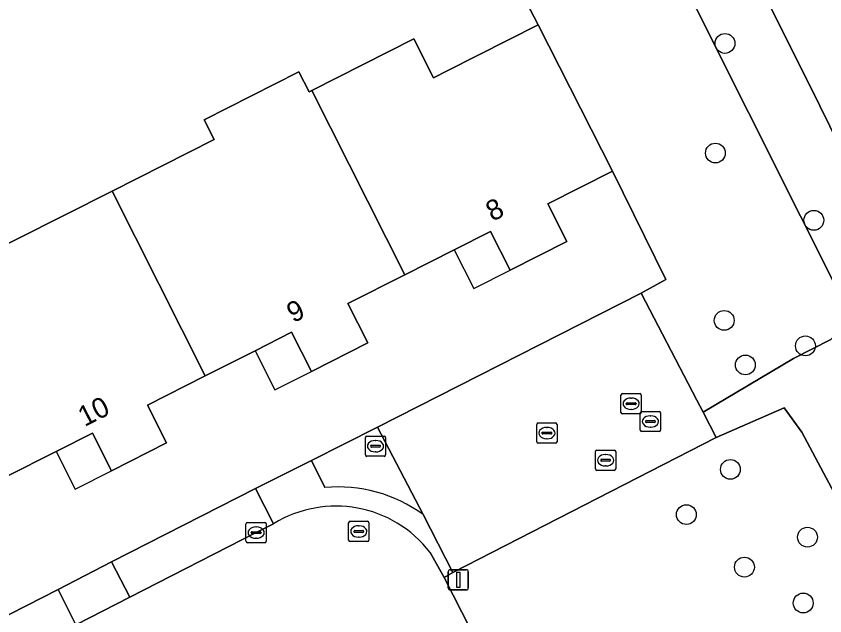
# Model space of a CAD drawing. Extents: x 162722 to 165104, y 384719 to 386284.
# Drawn here: x 163765.77 to 163805.66, y 385010 to 385039.57 of the extents above; entities that cross this region are included whole.
import ezdxf

# ---------------------------------------------------------------- set-up
doc = ezdxf.new("R2010")
doc.units = 0
for name, color, linetype in [('IMGEO_Boom', 7, 'Continuous'), ('IMGEO_Brandkraan', 7, 'Continuous'), ('IMGEO_Erf', 7, 'Continuous'), ('IMGEO_Groenvoorziening', 7, 'Continuous'), ('IMGEO_Kolk', 7, 'Continuous'), ('IMGEO_Lichtmast', 7, 'Continuous'), ('IMGEO_Pand', 7, 'Continuous'), ('IMGEO_Pand_nummerreeks', 7, 'Continuous'), ('IMGEO_Pand_overbouw', 7, 'Continuous'), ('IMGEO_Rijbaan_lokaal_open', 7, 'Continuous'), ('IMGEO_Rioolput', 7, 'Continuous'), ('IMGEO_Voetpad_open', 7, 'Continuous')]:
    doc.layers.add(name, color=color, linetype=linetype)

msp = doc.modelspace()

# ---------------------------------------------------------------- linework, layer by layer
at = {"layer": 'IMGEO_Boom'}
for centre in [(163800.734, 385038.222), (163800.261, 385032.816), (163805.118, 385029.501), (163800.696, 385024.566), (163804.702, 385023.309), (163801.74, 385022.369), (163801.001, 385017.219), (163798.83, 385014.99), (163804.803, 385013.876), (163801.694, 385012.4), (163804.593, 385010.631)]:
    msp.add_circle(centre, 0.489, dxfattribs=at)
at = {"layer": 'IMGEO_Brandkraan'}
for p, q in [((163782.997, 385017.937), (163782.997, 385018.789)), ((163783.072, 385018.863), (163783.924, 385018.863)), ((163783.998, 385018.789), (163783.998, 385017.937)), ((163783.256, 385018.357), (163783.256, 385018.369)), ((163783.694, 385018.32), (163783.296, 385018.32)), ((163783.299, 385018.406), (163783.697, 385018.406)), ((163783.485, 385018.643), (163783.51, 385018.643)), ((163783.74, 385018.369), (163783.74, 385018.357)), ((163783.924, 385017.863), (163783.072, 385017.863)), ((163783.508, 385018.083), (163783.483, 385018.083))]:
    msp.add_line(p, q, dxfattribs=at)
for points in [[(163782.997, 385017.937), (163782.997, 385018.789)], [(163783.072, 385018.863), (163783.924, 385018.863)], [(163783.998, 385018.789), (163783.998, 385017.937)], [(163783.924, 385017.863), (163783.072, 385017.863)]]:
    msp.add_lwpolyline(points, dxfattribs=at)
for centre, radius, start, end in [((163783.074, 385018.787), 0.0765, 91.552, 178.448), ((163783.074, 385018.787), 0.0765, 91.552, 178.448), ((163783.922, 385018.787), 0.0765, 1.552, 88.448), ((163783.922, 385018.787), 0.0765, 1.552, 88.448), ((163783.296, 385018.366), 0.0403, 85.8775, 175.7526), ((163783.293, 385018.356), 0.0366, 178.938, 274.7102), ((163783.697, 385018.363), 0.043, 264.8664, 352.4533), ((163783.701, 385018.368), 0.0386, 1.7309, 96.639), ((163783.074, 385017.939), 0.0765, 181.552, 268.448), ((163783.074, 385017.939), 0.0765, 181.552, 268.448), ((163783.922, 385017.939), 0.0765, 271.552, 358.448), ((163783.922, 385017.939), 0.0765, 271.552, 358.448)]:
    msp.add_arc(centre, radius, start, end, dxfattribs=at)
for centre, major_axis, ratio, start_param, end_param in [((163783.484, 385018.363), (-0.387, 0.002), 0.722429, 4.712389, 7.853982), ((163783.509, 385018.363), (-0.39, 0.002), 0.717154, 1.570796, 4.712389)]:
    msp.add_ellipse(centre, major_axis=major_axis, ratio=ratio, start_param=start_param, end_param=end_param, dxfattribs=at)
at = {"layer": 'IMGEO_Erf'}
for points in [[(163760.67, 385025.961), (163765.78, 385028.549), (163770.511, 385030.931), (163775.544, 385033.48), (163775.048, 385034.459), (163779.723, 385036.826), (163780.224, 385035.836), (163780.362, 385035.906), (163785.38, 385038.447), (163786.353, 385036.525), (163787.066, 385036.886), (163791.526, 385039.145), (163783.871, 385053.812)], [(163757.517, 385006.039), (163767.841, 385011.304), (163770.469, 385012.653), (163777.584, 385016.272), (163780.334, 385017.664), (163783.595, 385019.308), (163796.607, 385025.906), (163797.817, 385026.586), (163795.181, 385031.929), (163791.999, 385030.318), (163792.939, 385028.461), (163790.137, 385027.041), (163789.168, 385028.956), (163787.381, 385028.051), (163784.94, 385026.815), (163782.132, 385025.393), (163783.112, 385023.456), (163780.34, 385022.052), (163779.361, 385023.985), (163777.559, 385023.072), (163775.097, 385021.825), (163772.25, 385020.384), (163773.192, 385018.525), (163770.481, 385017.153), (163769.542, 385019.006), (163767.743, 385018.107), (163765.26, 385016.849)]]:
    msp.add_lwpolyline(points, dxfattribs=at)
at = {"layer": 'IMGEO_Groenvoorziening'}
msp.add_lwpolyline([(163776.799, 385086.81), (163778.131, 385085.393), (163779.162, 385082.093), (163791.359, 385057.157), (163791.535, 385054.401), (163792.881, 385051.428), (163794.209, 385050.139), (163807.026, 385024.596), (163808.566, 385025.713), (163809.035, 385026.84), (163808.847, 385028.154), (163805.421, 385035.138), (163798.727, 385048.566), (163793.575, 385058.788), (163790.143, 385065.128), (163788.181, 385067.57), (163786.027, 385073.647), (163785.482, 385074.719), (163784.543, 385076.561), (163782.934, 385079.72), (163780.143, 385084.723), (163778.682, 385086.223), (163777.874, 385086.761)], close=True, dxfattribs=at)
for points in [[(163783.871, 385053.812), (163791.526, 385039.145), (163795.181, 385031.929), (163797.817, 385026.586), (163796.607, 385025.906), (163799.345, 385020.634), (163799.657, 385020.033), (163804.115, 385022.684), (163805.95, 385023.625), (163807.026, 385024.596), (163794.209, 385050.139)], [(163798.727, 385048.566), (163805.421, 385035.138), (163808.847, 385028.154), (163809.035, 385026.84), (163808.566, 385025.713), (163807.026, 385024.596), (163805.95, 385023.625), (163804.115, 385022.684), (163799.657, 385020.033), (163800.305, 385018.786), (163803.653, 385020.249), (163804.532, 385019.055), (163810.006, 385008.789), (163813.545, 385004.677), (163817.003, 384998.463), (163818.75, 384994.205), (163821.467, 384989.96), (163821.501, 384989.907), (163826.306, 384989.862), (163827.686, 384987.569), (163834.379, 384974.661), (163840.9, 384963.114), (163856.826, 384929.784)], [(163810.006, 385008.789), (163804.532, 385019.055), (163803.653, 385020.249), (163800.305, 385018.786), (163787.306, 385012.139), (163786.877, 385011.884), (163792.143, 385001.568), (163792.25, 385001.396), (163802.343, 385006.509), (163805.625, 385000), (163810.019, 384991.283)]]:
    msp.add_lwpolyline(points, dxfattribs=at)
at = {"layer": 'IMGEO_Kolk'}
for p, q in [((163791.524, 385019.508), (163792.376, 385019.508)), ((163791.449, 385018.582), (163791.449, 385019.434)), ((163791.937, 385019.288), (163791.962, 385019.288)), ((163792.45, 385019.434), (163792.45, 385018.582)), ((163791.708, 385019.002), (163791.708, 385019.014)), ((163792.146, 385018.965), (163791.748, 385018.965)), ((163791.751, 385019.051), (163792.149, 385019.051)), ((163791.96, 385018.728), (163791.935, 385018.728)), ((163792.192, 385019.014), (163792.192, 385019.002)), ((163792.376, 385018.508), (163791.524, 385018.508)), ((163777.11, 385013.676), (163777.11, 385014.528)), ((163777.185, 385014.602), (163778.037, 385014.602)), ((163777.598, 385014.382), (163777.623, 385014.382)), ((163778.111, 385014.528), (163778.111, 385013.676)), ((163777.369, 385014.096), (163777.369, 385014.108)), ((163777.807, 385014.059), (163777.409, 385014.059)), ((163777.412, 385014.145), (163777.81, 385014.145)), ((163777.853, 385014.108), (163777.853, 385014.096)), ((163778.037, 385013.602), (163777.185, 385013.602)), ((163777.621, 385013.822), (163777.596, 385013.822))]:
    msp.add_line(p, q, dxfattribs=at)
for points in [[(163791.524, 385019.508), (163792.376, 385019.508)], [(163791.449, 385018.582), (163791.449, 385019.434)], [(163792.45, 385019.434), (163792.45, 385018.582)], [(163792.376, 385018.508), (163791.524, 385018.508)], [(163777.11, 385013.676), (163777.11, 385014.528)], [(163777.185, 385014.602), (163778.037, 385014.602)], [(163778.111, 385014.528), (163778.111, 385013.676)], [(163778.037, 385013.602), (163777.185, 385013.602)]]:
    msp.add_lwpolyline(points, dxfattribs=at)
for centre, radius, start, end in [((163791.526, 385019.432), 0.0765, 91.552, 178.448), ((163791.526, 385019.432), 0.0765, 91.552, 178.448), ((163792.374, 385019.432), 0.0765, 1.552, 88.448), ((163792.374, 385019.432), 0.0765, 1.552, 88.448), ((163791.748, 385019.011), 0.0403, 85.8775, 175.7526), ((163791.745, 385019.001), 0.0366, 178.938, 274.7102), ((163792.149, 385019.008), 0.043, 264.8664, 352.4533), ((163792.153, 385019.013), 0.0386, 1.7309, 96.639), ((163791.526, 385018.584), 0.0765, 181.552, 268.448), ((163791.526, 385018.584), 0.0765, 181.552, 268.448), ((163792.374, 385018.584), 0.0765, 271.552, 358.448), ((163792.374, 385018.584), 0.0765, 271.552, 358.448), ((163777.187, 385014.526), 0.0765, 91.552, 178.448), ((163777.187, 385014.526), 0.0765, 91.552, 178.448), ((163778.035, 385014.526), 0.0765, 1.552, 88.448), ((163778.035, 385014.526), 0.0765, 1.552, 88.448), ((163777.409, 385014.105), 0.0403, 85.8775, 175.7526), ((163777.406, 385014.095), 0.0366, 178.938, 274.7102), ((163777.81, 385014.102), 0.043, 264.8664, 352.4533), ((163777.814, 385014.107), 0.0386, 1.7309, 96.639), ((163777.187, 385013.678), 0.0765, 181.552, 268.448), ((163777.187, 385013.678), 0.0765, 181.552, 268.448), ((163778.035, 385013.678), 0.0765, 271.552, 358.448), ((163778.035, 385013.678), 0.0765, 271.552, 358.448)]:
    msp.add_arc(centre, radius, start, end, dxfattribs=at)
for centre, major_axis, ratio, start_param, end_param in [((163791.936, 385019.008), (-0.387, 0.002), 0.722429, 4.712389, 7.853982), ((163791.961, 385019.008), (-0.39, 0.002), 0.717154, 1.570796, 4.712389), ((163777.597, 385014.102), (-0.387, 0.002), 0.722429, 4.712389, 7.853982), ((163777.622, 385014.102), (-0.39, 0.002), 0.717154, 1.570796, 4.712389)]:
    msp.add_ellipse(centre, major_axis=major_axis, ratio=ratio, start_param=start_param, end_param=end_param, dxfattribs=at)
at = {"layer": 'IMGEO_Lichtmast'}
for p, q in [((163787.083, 385011.374), (163787.083, 385012.174)), ((163787.083, 385012.174), (163787.083, 385011.374)), ((163787.183, 385012.274), (163787.973, 385012.274)), ((163787.973, 385012.274), (163787.183, 385012.274)), ((163788.073, 385012.174), (163788.073, 385011.374)), ((163788.073, 385011.374), (163788.073, 385012.174)), ((163787.973, 385011.274), (163787.183, 385011.274)), ((163787.183, 385011.274), (163787.973, 385011.274))]:
    msp.add_line(p, q, dxfattribs=at)
msp.add_lwpolyline([(163787.503, 385012.149), (163787.653, 385012.149), (163787.653, 385011.399), (163787.503, 385011.399), (163787.503, 385012.149)], dxfattribs=at)
for centre, start, end in [((163787.183, 385012.174), 90, 180), ((163787.183, 385012.174), 90, 180), ((163787.973, 385012.174), 0, 90), ((163787.973, 385012.174), 360, 90), ((163787.183, 385011.374), 180, 270), ((163787.183, 385011.374), 180, 270), ((163787.973, 385011.374), 270, 0), ((163787.973, 385011.374), 270, 0)]:
    msp.add_arc(centre, 0.1, start, end, dxfattribs=at)
at = {"layer": 'IMGEO_Pand'}
for points in [[(163795.181, 385031.929), (163791.526, 385039.145), (163787.066, 385036.886), (163786.353, 385036.525), (163785.38, 385038.447), (163780.362, 385035.906), (163784.94, 385026.815), (163787.381, 385028.051), (163789.168, 385028.956), (163790.137, 385027.041), (163792.939, 385028.461), (163791.999, 385030.318)], [(163784.94, 385026.815), (163780.362, 385035.906), (163780.224, 385035.836), (163779.723, 385036.826), (163775.048, 385034.459), (163775.544, 385033.48), (163770.511, 385030.931), (163775.097, 385021.825), (163777.559, 385023.072), (163779.361, 385023.985), (163780.34, 385022.052), (163783.112, 385023.456), (163782.132, 385025.393)], [(163770.511, 385030.931), (163765.78, 385028.549), (163760.67, 385025.961), (163765.26, 385016.849), (163767.743, 385018.107), (163769.542, 385019.006), (163770.481, 385017.153), (163773.192, 385018.525), (163772.25, 385020.384), (163775.097, 385021.825)]]:
    msp.add_lwpolyline(points, close=True, dxfattribs=at)
at = {"layer": 'IMGEO_Pand_overbouw'}
for points in [[(163789.168, 385028.956), (163787.381, 385028.051), (163788.35, 385026.136), (163790.137, 385027.041)], [(163779.361, 385023.985), (163777.559, 385023.072), (163778.538, 385021.139), (163780.34, 385022.052)], [(163769.542, 385019.006), (163767.743, 385018.107), (163768.687, 385016.244), (163770.481, 385017.153)]]:
    msp.add_lwpolyline(points, close=True, dxfattribs=at)
at = {"layer": 'IMGEO_Rijbaan_lokaal_open'}
msp.add_lwpolyline([(163799.345, 385020.634), (163796.607, 385025.906), (163783.595, 385019.308), (163785.848, 385014.991), (163787.306, 385012.139), (163800.305, 385018.786), (163799.657, 385020.033)], close=True, dxfattribs=at)
for points in [[(163778.469, 385014.536), (163777.611, 385014.102), (163771.379, 385010.915), (163768.724, 385009.555), (163768.327, 385009.356), (163758.942, 385004.57), (163762.509, 384997.523)], [(163786.877, 385011.884), (163786.194, 385013.124)], [(163772.832, 384984.93), (163774.567, 384986.495), (163774.901, 384986.825), (163781.701, 384993.056), (163789.311, 385000), (163789.58, 385000.245), (163792.25, 385001.396), (163792.143, 385001.568), (163786.877, 385011.884)]]:
    msp.add_lwpolyline(points, dxfattribs=at)
msp.add_arc((163781.548, 385009.542), 5.867, 37.6313, 121.652, dxfattribs=at)
at = {"layer": 'IMGEO_Rioolput'}
for p, q in [((163795.605, 385020.031), (163795.605, 385020.883)), ((163795.68, 385020.957), (163796.532, 385020.957)), ((163796.093, 385020.737), (163796.118, 385020.737)), ((163796.606, 385020.883), (163796.606, 385020.031)), ((163795.864, 385020.451), (163795.864, 385020.463)), ((163796.302, 385020.414), (163795.904, 385020.414)), ((163795.907, 385020.5), (163796.305, 385020.5)), ((163796.348, 385020.463), (163796.348, 385020.451)), ((163796.532, 385019.957), (163795.68, 385019.957)), ((163796.116, 385020.177), (163796.091, 385020.177)), ((163796.558, 385019.154), (163796.558, 385020.006)), ((163796.633, 385020.08), (163797.485, 385020.08)), ((163797.046, 385019.86), (163797.071, 385019.86)), ((163797.559, 385020.006), (163797.559, 385019.154)), ((163796.817, 385019.574), (163796.817, 385019.586)), ((163797.255, 385019.537), (163796.857, 385019.537)), ((163796.86, 385019.623), (163797.258, 385019.623)), ((163797.301, 385019.586), (163797.301, 385019.574)), ((163797.485, 385019.08), (163796.633, 385019.08)), ((163797.069, 385019.3), (163797.044, 385019.3)), ((163794.346, 385017.246), (163794.346, 385018.098)), ((163794.421, 385018.172), (163795.273, 385018.172)), ((163794.834, 385017.952), (163794.859, 385017.952)), ((163795.347, 385018.098), (163795.347, 385017.246)), ((163794.605, 385017.666), (163794.605, 385017.678)), ((163795.043, 385017.629), (163794.645, 385017.629)), ((163794.648, 385017.715), (163795.046, 385017.715)), ((163795.089, 385017.678), (163795.089, 385017.666)), ((163795.273, 385017.172), (163794.421, 385017.172)), ((163794.857, 385017.392), (163794.832, 385017.392)), ((163782.173, 385013.732), (163782.173, 385014.584)), ((163782.248, 385014.658), (163783.1, 385014.658)), ((163782.661, 385014.438), (163782.686, 385014.438)), ((163783.174, 385014.584), (163783.174, 385013.732)), ((163782.432, 385014.152), (163782.432, 385014.164)), ((163782.87, 385014.115), (163782.472, 385014.115)), ((163782.475, 385014.201), (163782.873, 385014.201)), ((163782.684, 385013.878), (163782.659, 385013.878)), ((163782.916, 385014.164), (163782.916, 385014.152)), ((163783.1, 385013.658), (163782.248, 385013.658))]:
    msp.add_line(p, q, dxfattribs=at)
for points in [[(163795.605, 385020.031), (163795.605, 385020.883)], [(163795.68, 385020.957), (163796.532, 385020.957)], [(163796.606, 385020.883), (163796.606, 385020.031)], [(163796.532, 385019.957), (163795.68, 385019.957)], [(163796.558, 385019.154), (163796.558, 385020.006)], [(163796.633, 385020.08), (163797.485, 385020.08)], [(163797.559, 385020.006), (163797.559, 385019.154)], [(163797.485, 385019.08), (163796.633, 385019.08)], [(163794.346, 385017.246), (163794.346, 385018.098)], [(163794.421, 385018.172), (163795.273, 385018.172)], [(163795.347, 385018.098), (163795.347, 385017.246)], [(163795.273, 385017.172), (163794.421, 385017.172)], [(163782.173, 385013.732), (163782.173, 385014.584)], [(163782.248, 385014.658), (163783.1, 385014.658)], [(163783.174, 385014.584), (163783.174, 385013.732)], [(163783.1, 385013.658), (163782.248, 385013.658)]]:
    msp.add_lwpolyline(points, dxfattribs=at)
for centre, radius, start, end in [((163795.682, 385020.881), 0.0765, 91.552, 178.448), ((163795.682, 385020.881), 0.0765, 91.552, 178.448), ((163796.53, 385020.881), 0.0765, 1.552, 88.448), ((163796.53, 385020.881), 0.0765, 1.552, 88.448), ((163795.904, 385020.46), 0.0403, 85.8775, 175.7526), ((163795.901, 385020.45), 0.0366, 178.938, 274.7102), ((163796.305, 385020.457), 0.043, 264.8664, 352.4533), ((163796.309, 385020.462), 0.0386, 1.7309, 96.639), ((163795.682, 385020.033), 0.0765, 181.552, 268.448), ((163795.682, 385020.033), 0.0765, 181.552, 268.448), ((163796.53, 385020.033), 0.0765, 271.552, 358.448), ((163796.53, 385020.033), 0.0765, 271.552, 358.448), ((163796.635, 385020.004), 0.0765, 91.552, 178.448), ((163796.635, 385020.004), 0.0765, 91.552, 178.448), ((163797.483, 385020.004), 0.0765, 1.552, 88.448), ((163797.483, 385020.004), 0.0765, 1.552, 88.448), ((163796.857, 385019.583), 0.0403, 85.8775, 175.7526), ((163796.854, 385019.573), 0.0366, 178.938, 274.7102), ((163797.258, 385019.58), 0.043, 264.8664, 352.4533), ((163797.262, 385019.585), 0.0386, 1.7309, 96.639), ((163796.635, 385019.156), 0.0765, 181.552, 268.448), ((163796.635, 385019.156), 0.0765, 181.552, 268.448), ((163797.483, 385019.156), 0.0765, 271.552, 358.448), ((163797.483, 385019.156), 0.0765, 271.552, 358.448), ((163794.423, 385018.096), 0.0765, 91.552, 178.448), ((163794.423, 385018.096), 0.0765, 91.552, 178.448), ((163795.271, 385018.096), 0.0765, 1.552, 88.448), ((163795.271, 385018.096), 0.0765, 1.552, 88.448), ((163794.645, 385017.675), 0.0403, 85.8775, 175.7526), ((163794.642, 385017.665), 0.0366, 178.938, 274.7102), ((163795.046, 385017.672), 0.043, 264.8664, 352.4533), ((163795.05, 385017.677), 0.0386, 1.7309, 96.639), ((163794.423, 385017.248), 0.0765, 181.552, 268.448), ((163794.423, 385017.248), 0.0765, 181.552, 268.448), ((163795.271, 385017.248), 0.0765, 271.552, 358.448), ((163795.271, 385017.248), 0.0765, 271.552, 358.448), ((163782.25, 385014.582), 0.0765, 91.552, 178.448), ((163782.25, 385014.582), 0.0765, 91.552, 178.448), ((163783.098, 385014.582), 0.0765, 1.552, 88.448), ((163783.098, 385014.582), 0.0765, 1.552, 88.448), ((163782.472, 385014.161), 0.0403, 85.8775, 175.7526), ((163782.469, 385014.151), 0.0366, 178.938, 274.7102), ((163782.873, 385014.158), 0.043, 264.8664, 352.4533), ((163782.877, 385014.163), 0.0386, 1.7309, 96.639), ((163782.25, 385013.734), 0.0765, 181.552, 268.448), ((163782.25, 385013.734), 0.0765, 181.552, 268.448), ((163783.098, 385013.734), 0.0765, 271.552, 358.448), ((163783.098, 385013.734), 0.0765, 271.552, 358.448)]:
    msp.add_arc(centre, radius, start, end, dxfattribs=at)
for centre, major_axis, ratio, start_param, end_param in [((163796.092, 385020.457), (-0.387, 0.002), 0.722429, 4.712389, 7.853982), ((163796.117, 385020.457), (-0.39, 0.002), 0.717154, 1.570796, 4.712389), ((163797.045, 385019.58), (-0.387, 0.002), 0.722429, 4.712389, 7.853982), ((163797.07, 385019.58), (-0.39, 0.002), 0.717154, 1.570796, 4.712389), ((163794.833, 385017.672), (-0.387, 0.002), 0.722429, 4.712389, 7.853982), ((163794.858, 385017.672), (-0.39, 0.002), 0.717154, 1.570796, 4.712389), ((163782.66, 385014.158), (-0.387, 0.002), 0.722429, 4.712389, 7.853982), ((163782.685, 385014.158), (-0.39, 0.002), 0.717154, 1.570796, 4.712389)]:
    msp.add_ellipse(centre, major_axis=major_axis, ratio=ratio, start_param=start_param, end_param=end_param, dxfattribs=at)
at = {"layer": 'IMGEO_Voetpad_open'}
for points in [[(163785.848, 385014.991), (163783.595, 385019.308), (163780.334, 385017.664), (163781.003, 385016.322)], [(163781.003, 385016.322), (163780.334, 385017.664), (163777.584, 385016.272), (163778.469, 385014.536)], [(163786.194, 385013.124), (163786.877, 385011.884), (163787.306, 385012.139), (163785.848, 385014.991)]]:
    msp.add_lwpolyline(points, dxfattribs=at)
for points in [[(163771.379, 385010.915), (163777.611, 385014.102), (163778.469, 385014.536), (163777.584, 385016.272), (163770.469, 385012.653)], [(163770.469, 385012.653), (163767.841, 385011.304), (163768.724, 385009.555), (163771.379, 385010.915)], [(163768.327, 385009.356), (163768.724, 385009.555), (163767.841, 385011.304), (163757.517, 385006.039), (163757.459, 385006.177), (163753.157, 385003.995), (163753.91, 385002.58), (163758.314, 385004.819), (163758.54, 385004.374), (163758.942, 385004.57)]]:
    msp.add_lwpolyline(points, close=True, dxfattribs=at)
for centre, radius, start, end in [((163781.665, 385009.246), 7.106, 53.9363, 95.3415), ((163781.665, 385009.246), 7.106, 53.9363, 95.3415), ((163781.548, 385009.542), 5.867, 37.6313, 121.652)]:
    msp.add_arc(centre, radius, start, end, dxfattribs=at)

# ---------------------------------------------------------------- texts
at = {"layer": 'IMGEO_Pand_nummerreeks'}
for s, rotation, p in [('8', 26.8717, (163789.264, 385029.423)), ('9', 26.866, (163779.442, 385024.421)), ('10', 26.8545, (163769.148, 385019.302))]:
    msp.add_text(s, height=1, rotation=rotation, dxfattribs=at).set_placement(p)

doc.saveas('drawing.dxf')
